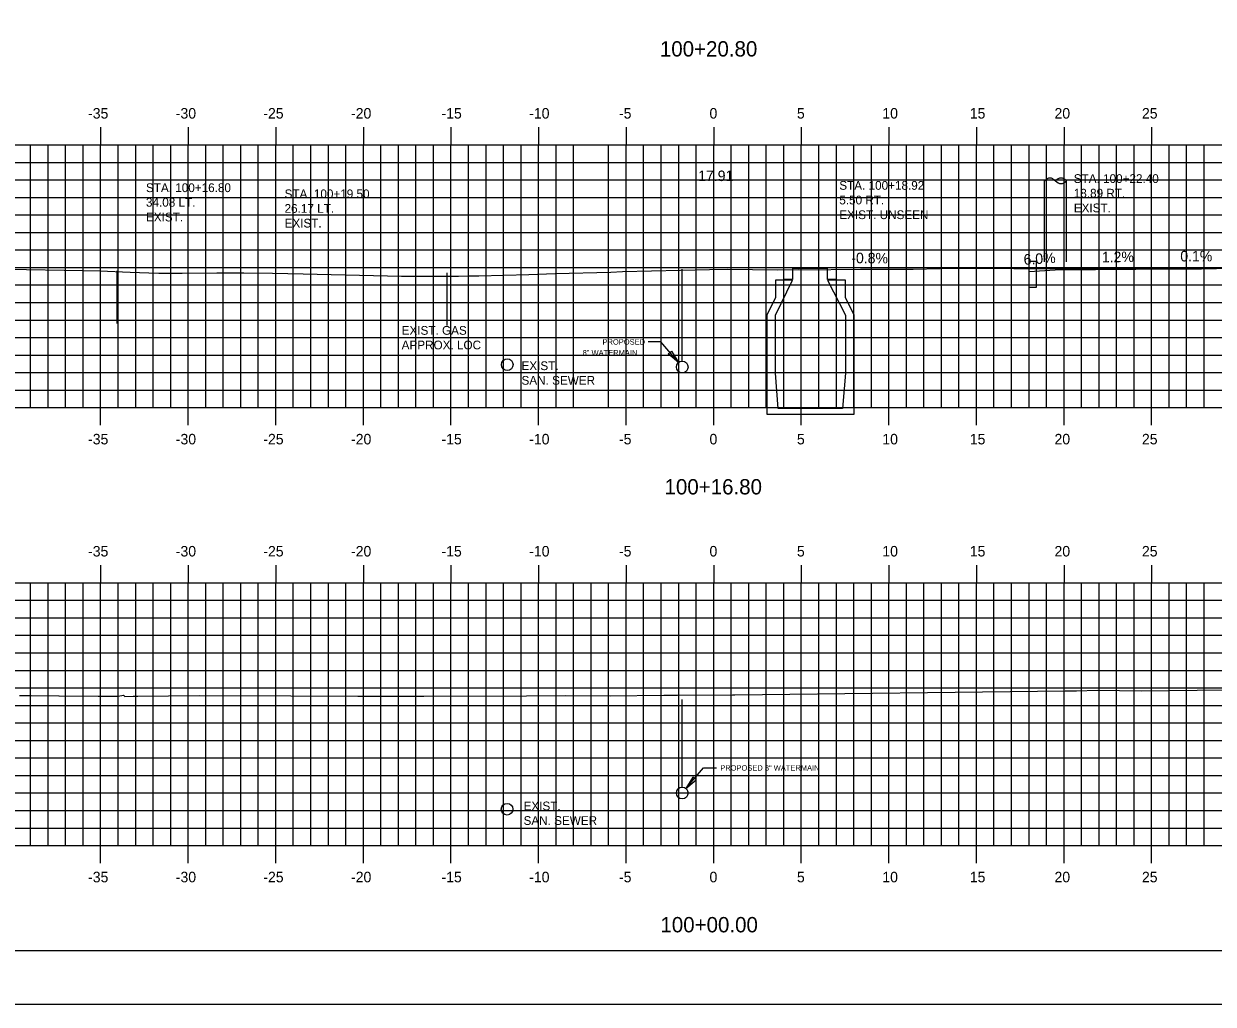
# Model space of a CAD drawing. Extents: x 1023237 to 1023407, y 394697 to 394807.
# Drawn here: x 1023280.3 to 1023348.2, y 394696.5 to 394752.5 of the extents above; entities that cross this region are included whole.
import ezdxf

# ---------------------------------------------------------------- set-up
doc = ezdxf.new("R2010")
doc.units = 0
for name, color, linetype in [('ANNOTATION', 7, 'Continuous'), ('BORDER', 7, 'Continuous'), ('D_Curb_Type_1_Rt', 7, 'Continuous'), ('D_Roadway_Berm', 7, 'Continuous'), ('D_Roadway_Centerline', 7, 'Continuous'), ('D_Roadway_Centerline_Text', 7, 'Continuous'), ('D_Roadway_SlopeLines', 7, 'Continuous'), ('D_Text_Monospaced', 7, 'Continuous'), ('H_V ANNOTATION', 7, 'Continuous'), ('MAJOR', 7, 'Continuous'), ('MINOR', 7, 'Continuous'), ('p-water', 7, 'Continuous'), ('p-water-text', 7, 'Continuous'), ('PLOT BOUNDARY', 7, 'Continuous'), ('S_Drainage_MH', 7, 'Continuous'), ('S_Roadway_Centerline', 7, 'Continuous'), ('S_Utilities_Pole_Power', 7, 'Continuous'), ('S_Utilities_UG_Gas_Line', 7, 'Continuous'), ('S_Utilities_UG_Sanitary_Sewer', 7, 'Continuous')]:
    doc.layers.add(name, color=color, linetype=linetype)

msp = doc.modelspace()

# ---------------------------------------------------------------- linework, layer by layer
at = {"layer": 'BORDER'}
msp.add_line((1023244.664, 394699.607), (1023404.664, 394699.607), dxfattribs=at)
at = {"layer": 'D_Curb_Type_1_Rt'}
msp.add_lwpolyline([(1023338.08, 394738.957), (1023338.08, 394737.457), (1023337.663, 394737.457), (1023337.663, 394738.957)], close=True, dxfattribs=at)
at = {"layer": 'D_Roadway_Berm'}
msp.add_lwpolyline([(1023337.663, 394738.374), (1023339.163, 394738.464)], dxfattribs=at)
at = {"layer": 'D_Roadway_SlopeLines'}
msp.add_lwpolyline([(1023339.163, 394738.464), (1023362.163, 394738.659)], dxfattribs=at)
at = {"layer": 'MAJOR'}
for p, q in [((1023284.663, 394746.609), (1023284.663, 394745.607)), ((1023289.663, 394746.609), (1023289.663, 394745.607)), ((1023294.663, 394746.609), (1023294.663, 394745.607)), ((1023299.663, 394746.609), (1023299.663, 394745.607)), ((1023304.663, 394746.609), (1023304.663, 394745.607)), ((1023309.663, 394746.609), (1023309.663, 394745.607)), ((1023314.663, 394746.609), (1023314.663, 394745.607)), ((1023319.663, 394746.609), (1023319.663, 394745.607)), ((1023324.663, 394746.609), (1023324.663, 394745.607)), ((1023329.663, 394746.609), (1023329.663, 394745.607)), ((1023334.663, 394746.609), (1023334.663, 394745.607)), ((1023339.663, 394746.609), (1023339.663, 394745.607)), ((1023344.663, 394746.609), (1023344.663, 394745.607)), ((1023249.663, 394745.607), (1023389.663, 394745.607)), ((1023284.663, 394730.607), (1023284.663, 394745.607)), ((1023289.663, 394730.607), (1023289.663, 394745.607)), ((1023294.663, 394730.607), (1023294.663, 394745.607)), ((1023299.663, 394730.607), (1023299.663, 394745.607)), ((1023304.663, 394730.607), (1023304.663, 394745.607)), ((1023309.663, 394730.607), (1023309.663, 394745.607)), ((1023314.663, 394730.607), (1023314.663, 394745.607)), ((1023319.663, 394730.607), (1023319.663, 394745.607)), ((1023324.663, 394730.607), (1023324.663, 394745.607)), ((1023329.663, 394730.607), (1023329.663, 394745.607)), ((1023334.663, 394730.607), (1023334.663, 394745.607)), ((1023339.663, 394730.607), (1023339.663, 394745.607)), ((1023344.663, 394730.607), (1023344.663, 394745.607)), ((1023249.663, 394740.607), (1023389.663, 394740.607)), ((1023249.663, 394735.607), (1023389.663, 394735.607)), ((1023249.663, 394730.607), (1023389.663, 394730.607)), ((1023284.663, 394729.605), (1023284.663, 394730.607)), ((1023289.663, 394729.605), (1023289.663, 394730.607)), ((1023294.663, 394729.605), (1023294.663, 394730.607)), ((1023299.663, 394729.605), (1023299.663, 394730.607)), ((1023304.663, 394729.605), (1023304.663, 394730.607)), ((1023309.663, 394729.605), (1023309.663, 394730.607)), ((1023314.663, 394729.605), (1023314.663, 394730.607)), ((1023319.663, 394729.605), (1023319.663, 394730.607)), ((1023324.663, 394729.605), (1023324.663, 394730.607)), ((1023329.663, 394729.605), (1023329.663, 394730.607)), ((1023334.663, 394729.605), (1023334.663, 394730.607)), ((1023339.663, 394729.605), (1023339.663, 394730.607)), ((1023344.663, 394729.605), (1023344.663, 394730.607)), ((1023284.663, 394721.609), (1023284.663, 394720.607)), ((1023289.663, 394721.609), (1023289.663, 394720.607)), ((1023294.663, 394721.609), (1023294.663, 394720.607)), ((1023299.663, 394721.609), (1023299.663, 394720.607)), ((1023304.663, 394721.609), (1023304.663, 394720.607)), ((1023309.663, 394721.609), (1023309.663, 394720.607)), ((1023314.663, 394721.609), (1023314.663, 394720.607)), ((1023319.663, 394721.609), (1023319.663, 394720.607)), ((1023324.663, 394721.609), (1023324.663, 394720.607)), ((1023329.663, 394721.609), (1023329.663, 394720.607)), ((1023334.663, 394721.609), (1023334.663, 394720.607)), ((1023339.663, 394721.609), (1023339.663, 394720.607)), ((1023344.663, 394721.609), (1023344.663, 394720.607)), ((1023249.663, 394720.607), (1023389.663, 394720.607)), ((1023284.663, 394705.607), (1023284.663, 394720.607)), ((1023289.663, 394705.607), (1023289.663, 394720.607)), ((1023294.663, 394705.607), (1023294.663, 394720.607)), ((1023299.663, 394705.607), (1023299.663, 394720.607)), ((1023304.663, 394705.607), (1023304.663, 394720.607)), ((1023309.663, 394705.607), (1023309.663, 394720.607)), ((1023314.663, 394705.607), (1023314.663, 394720.607)), ((1023319.663, 394705.607), (1023319.663, 394720.607)), ((1023324.663, 394705.607), (1023324.663, 394720.607)), ((1023329.663, 394705.607), (1023329.663, 394720.607)), ((1023334.663, 394705.607), (1023334.663, 394720.607)), ((1023339.663, 394705.607), (1023339.663, 394720.607)), ((1023344.663, 394705.607), (1023344.663, 394720.607)), ((1023249.663, 394715.607), (1023389.663, 394715.607)), ((1023249.663, 394710.607), (1023389.663, 394710.607)), ((1023249.663, 394705.607), (1023389.663, 394705.607)), ((1023284.663, 394704.605), (1023284.663, 394705.607)), ((1023289.663, 394704.605), (1023289.663, 394705.607)), ((1023294.663, 394704.605), (1023294.663, 394705.607)), ((1023299.663, 394704.605), (1023299.663, 394705.607)), ((1023304.663, 394704.605), (1023304.663, 394705.607)), ((1023309.663, 394704.605), (1023309.663, 394705.607)), ((1023314.663, 394704.605), (1023314.663, 394705.607)), ((1023319.663, 394704.605), (1023319.663, 394705.607)), ((1023324.663, 394704.605), (1023324.663, 394705.607)), ((1023329.663, 394704.605), (1023329.663, 394705.607)), ((1023334.663, 394704.605), (1023334.663, 394705.607)), ((1023339.663, 394704.605), (1023339.663, 394705.607)), ((1023344.663, 394704.605), (1023344.663, 394705.607))]:
    msp.add_line(p, q, dxfattribs=at)
at = {"layer": 'MINOR'}
for p, q in [((1023280.663, 394730.607), (1023280.663, 394745.607)), ((1023281.663, 394730.607), (1023281.663, 394745.607)), ((1023282.663, 394730.607), (1023282.663, 394745.607)), ((1023283.663, 394730.607), (1023283.663, 394745.607)), ((1023285.663, 394730.607), (1023285.663, 394745.607)), ((1023286.663, 394730.607), (1023286.663, 394745.607)), ((1023287.663, 394730.607), (1023287.663, 394745.607)), ((1023288.663, 394730.607), (1023288.663, 394745.607)), ((1023290.663, 394730.607), (1023290.663, 394745.607)), ((1023291.663, 394730.607), (1023291.663, 394745.607)), ((1023292.663, 394730.607), (1023292.663, 394745.607)), ((1023293.663, 394730.607), (1023293.663, 394745.607)), ((1023295.663, 394730.607), (1023295.663, 394745.607)), ((1023296.663, 394730.607), (1023296.663, 394745.607)), ((1023297.663, 394730.607), (1023297.663, 394745.607)), ((1023298.663, 394730.607), (1023298.663, 394745.607)), ((1023300.663, 394730.607), (1023300.663, 394745.607)), ((1023301.663, 394730.607), (1023301.663, 394745.607)), ((1023302.663, 394730.607), (1023302.663, 394745.607)), ((1023303.663, 394730.607), (1023303.663, 394745.607)), ((1023305.663, 394730.607), (1023305.663, 394745.607)), ((1023306.663, 394730.607), (1023306.663, 394745.607)), ((1023307.663, 394730.607), (1023307.663, 394745.607)), ((1023308.663, 394730.607), (1023308.663, 394745.607)), ((1023310.663, 394730.607), (1023310.663, 394745.607)), ((1023311.663, 394730.607), (1023311.663, 394745.607)), ((1023313.663, 394730.607), (1023313.663, 394745.607)), ((1023315.663, 394730.607), (1023315.663, 394745.607)), ((1023316.663, 394730.607), (1023316.663, 394745.607)), ((1023317.663, 394730.607), (1023317.663, 394745.607)), ((1023318.663, 394730.607), (1023318.663, 394745.607)), ((1023320.663, 394730.607), (1023320.663, 394745.607)), ((1023321.663, 394730.607), (1023321.663, 394745.607)), ((1023322.663, 394730.607), (1023322.663, 394745.607)), ((1023323.663, 394730.607), (1023323.663, 394745.607)), ((1023325.663, 394730.607), (1023325.663, 394745.607)), ((1023326.663, 394730.607), (1023326.663, 394745.607)), ((1023327.663, 394730.607), (1023327.663, 394745.607)), ((1023328.663, 394730.607), (1023328.663, 394745.607)), ((1023330.663, 394730.607), (1023330.663, 394745.607)), ((1023331.663, 394730.607), (1023331.663, 394745.607)), ((1023332.663, 394730.607), (1023332.663, 394745.607)), ((1023333.663, 394730.607), (1023333.663, 394745.607)), ((1023335.663, 394730.607), (1023335.663, 394745.607)), ((1023336.663, 394730.607), (1023336.663, 394745.607)), ((1023337.663, 394730.607), (1023337.663, 394745.607)), ((1023338.663, 394730.607), (1023338.663, 394745.607)), ((1023340.663, 394730.607), (1023340.663, 394745.607)), ((1023341.663, 394730.607), (1023341.663, 394745.607)), ((1023342.663, 394730.607), (1023342.663, 394745.607)), ((1023343.663, 394730.607), (1023343.663, 394745.607)), ((1023345.663, 394730.607), (1023345.663, 394745.607)), ((1023346.663, 394730.607), (1023346.663, 394745.607)), ((1023347.663, 394730.607), (1023347.663, 394745.607)), ((1023249.663, 394744.607), (1023389.663, 394744.607)), ((1023249.663, 394743.607), (1023389.663, 394743.607)), ((1023249.663, 394742.607), (1023389.663, 394742.607)), ((1023249.663, 394741.607), (1023389.663, 394741.607)), ((1023249.663, 394739.607), (1023389.663, 394739.607)), ((1023249.663, 394738.607), (1023389.663, 394738.607)), ((1023249.663, 394737.607), (1023389.663, 394737.607)), ((1023249.663, 394736.607), (1023389.663, 394736.607)), ((1023249.663, 394734.607), (1023389.663, 394734.607)), ((1023249.663, 394733.607), (1023389.663, 394733.607)), ((1023249.663, 394732.607), (1023389.663, 394732.607)), ((1023249.663, 394731.607), (1023389.663, 394731.607)), ((1023280.663, 394705.607), (1023280.663, 394720.607)), ((1023281.663, 394705.607), (1023281.663, 394720.607)), ((1023282.663, 394705.607), (1023282.663, 394720.607)), ((1023283.663, 394705.607), (1023283.663, 394720.607)), ((1023285.663, 394705.607), (1023285.663, 394720.607)), ((1023286.663, 394705.607), (1023286.663, 394720.607)), ((1023287.663, 394705.607), (1023287.663, 394720.607)), ((1023288.663, 394705.607), (1023288.663, 394720.607)), ((1023290.663, 394705.607), (1023290.663, 394720.607)), ((1023291.663, 394705.607), (1023291.663, 394720.607)), ((1023292.663, 394705.607), (1023292.663, 394720.607)), ((1023293.663, 394705.607), (1023293.663, 394720.607)), ((1023295.663, 394705.607), (1023295.663, 394720.607)), ((1023296.663, 394705.607), (1023296.663, 394720.607)), ((1023297.663, 394705.607), (1023297.663, 394720.607)), ((1023298.663, 394705.607), (1023298.663, 394720.607)), ((1023300.663, 394705.607), (1023300.663, 394720.607)), ((1023301.663, 394705.607), (1023301.663, 394720.607)), ((1023302.663, 394705.607), (1023302.663, 394720.607)), ((1023303.663, 394705.607), (1023303.663, 394720.607)), ((1023305.663, 394705.607), (1023305.663, 394720.607)), ((1023306.663, 394705.607), (1023306.663, 394720.607)), ((1023307.663, 394705.607), (1023307.663, 394720.607)), ((1023308.663, 394705.607), (1023308.663, 394720.607)), ((1023310.663, 394705.607), (1023310.663, 394720.607)), ((1023311.663, 394705.607), (1023311.663, 394720.607)), ((1023312.663, 394705.607), (1023312.663, 394720.607)), ((1023313.663, 394705.607), (1023313.663, 394720.607)), ((1023315.663, 394705.607), (1023315.663, 394720.607)), ((1023316.663, 394705.607), (1023316.663, 394720.607)), ((1023317.663, 394705.607), (1023317.663, 394720.607)), ((1023318.663, 394705.607), (1023318.663, 394720.607)), ((1023320.663, 394705.607), (1023320.663, 394720.607)), ((1023321.663, 394705.607), (1023321.663, 394720.607)), ((1023322.663, 394705.607), (1023322.663, 394720.607)), ((1023323.663, 394705.607), (1023323.663, 394720.607)), ((1023325.663, 394705.607), (1023325.663, 394720.607)), ((1023326.663, 394705.607), (1023326.663, 394720.607)), ((1023327.663, 394705.607), (1023327.663, 394720.607)), ((1023328.663, 394705.607), (1023328.663, 394720.607)), ((1023330.663, 394705.607), (1023330.663, 394720.607)), ((1023331.663, 394705.607), (1023331.663, 394720.607)), ((1023332.663, 394705.607), (1023332.663, 394720.607)), ((1023333.663, 394705.607), (1023333.663, 394720.607)), ((1023335.663, 394705.607), (1023335.663, 394720.607)), ((1023336.663, 394705.607), (1023336.663, 394720.607)), ((1023337.663, 394705.607), (1023337.663, 394720.607)), ((1023338.663, 394705.607), (1023338.663, 394720.607)), ((1023340.663, 394705.607), (1023340.663, 394720.607)), ((1023341.663, 394705.607), (1023341.663, 394720.607)), ((1023342.663, 394705.607), (1023342.663, 394720.607)), ((1023343.663, 394705.607), (1023343.663, 394720.607)), ((1023345.663, 394705.607), (1023345.663, 394720.607)), ((1023346.663, 394705.607), (1023346.663, 394720.607)), ((1023347.663, 394705.607), (1023347.663, 394720.607)), ((1023249.663, 394719.607), (1023389.663, 394719.607)), ((1023249.663, 394718.607), (1023389.663, 394718.607)), ((1023249.663, 394717.607), (1023389.663, 394717.607)), ((1023249.663, 394716.607), (1023389.663, 394716.607)), ((1023249.663, 394714.607), (1023389.663, 394714.607)), ((1023249.663, 394713.607), (1023389.663, 394713.607)), ((1023249.663, 394712.607), (1023389.663, 394712.607)), ((1023249.663, 394711.607), (1023389.663, 394711.607)), ((1023249.663, 394709.607), (1023389.663, 394709.607)), ((1023249.663, 394708.607), (1023389.663, 394708.607)), ((1023249.663, 394707.607), (1023389.663, 394707.607)), ((1023249.663, 394706.607), (1023389.663, 394706.607))]:
    msp.add_line(p, q, dxfattribs=at)
at = {"layer": 'p-water'}
msp.add_line((1023317.865, 394733.257), (1023317.865, 394738.507), dxfattribs=at)
msp.add_lwpolyline([(1023317.865, 394708.936), (1023317.865, 394713.936)], dxfattribs=at)
for centre in [(1023317.865, 394732.924), (1023317.865, 394708.603)]:
    msp.add_circle(centre, 0.333, dxfattribs=at)
at = {"layer": 'p-water-text'}
for points in [[(1023317.649, 394733.178), (1023316.646, 394734.355), (1023315.913, 394734.355)], [(1023318.079, 394708.859), (1023319.082, 394710.036), (1023319.815, 394710.036)]]:
    msp.add_lwpolyline(points, dxfattribs=at)
for points in [[(1023317.068, 394733.668), (1023317.258, 394733.83), (1023317.649, 394733.178)], [(1023318.66, 394709.349), (1023318.47, 394709.511), (1023318.079, 394708.859)]]:
    msp.add_lwpolyline(points, close=True, dxfattribs=at)
at = {"layer": 'PLOT BOUNDARY'}
msp.add_lwpolyline([(1023236.57, 394696.548), (1023406.57, 394696.548), (1023406.57, 394806.548), (1023236.57, 394806.548)], close=True, dxfattribs=at)
at = {"layer": 'S_Drainage_MH'}
for p, q in [((1023324.165, 394737.879), (1023323.181, 394737.879)), ((1023323.181, 394737.879), (1023323.181, 394736.895)), ((1023323.181, 394735.878), (1023324.165, 394737.879)), ((1023327.183, 394737.879), (1023326.166, 394737.879)), ((1023326.166, 394737.879), (1023327.183, 394735.878)), ((1023327.183, 394736.895), (1023327.183, 394737.879)), ((1023323.181, 394736.895), (1023322.688, 394735.878)), ((1023327.675, 394735.878), (1023327.183, 394736.895)), ((1023322.688, 394735.878), (1023322.688, 394730.235)), ((1023323.181, 394732.564), (1023323.181, 394735.878)), ((1023327.183, 394735.878), (1023327.183, 394732.564)), ((1023327.675, 394730.235), (1023327.675, 394735.878)), ((1023323.345, 394730.563), (1023323.181, 394732.564)), ((1023327.183, 394732.564), (1023327.019, 394730.563)), ((1023322.688, 394730.235), (1023327.675, 394730.235)), ((1023327.019, 394730.563), (1023323.345, 394730.563))]:
    msp.add_line(p, q, dxfattribs=at)
msp.add_lwpolyline([(1023326.658, 394737.921), (1023326.166, 394737.921), (1023326.166, 394738.544), (1023324.165, 394738.544), (1023324.165, 394737.921), (1023323.673, 394737.921)], dxfattribs=at)
at = {"layer": 'S_Roadway_Centerline'}
for points in [[(1023279.356, 394738.503), (1023283.639, 394738.442), (1023284.613, 394738.41), (1023286.353, 394738.34), (1023287.409, 394738.298), (1023287.978, 394738.275), (1023289.319, 394738.283), (1023291.289, 394738.299), (1023292.834, 394738.302), (1023294.482, 394738.289), (1023296.226, 394738.238), (1023301.837, 394738.105), (1023302.283, 394738.114), (1023303.112, 394738.115), (1023305.088, 394738.108), (1023305.641, 394738.124), (1023306.25, 394738.132), (1023309.111, 394738.214), (1023310.616, 394738.254), (1023313.789, 394738.348), (1023314.452, 394738.382), (1023319.414, 394738.497), (1023320.465, 394738.51), (1023323.281, 394738.475), (1023324.509, 394738.493), (1023324.674, 394738.476), (1023328.034, 394738.512), (1023331.043, 394738.506), (1023332.593, 394738.551), (1023335.834, 394738.561), (1023336.595, 394738.56), (1023336.793, 394738.545), (1023337.2, 394738.549), (1023337.268, 394738.548), (1023341.123, 394738.542), (1023343.602, 394738.533), (1023345.21, 394738.526), (1023347.511, 394738.538), (1023349.628, 394738.643)], [(1023280.039, 394714.166), (1023280.7, 394714.164), (1023282.28, 394714.155), (1023282.295, 394714.156), (1023284.525, 394714.138), (1023284.92, 394714.138), (1023285.666, 394714.125), (1023285.96, 394714.182), (1023286.037, 394714.123), (1023286.522, 394714.125), (1023286.746, 394714.125), (1023286.781, 394714.125), (1023290.283, 394714.168), (1023295.53, 394714.143), (1023299.347, 394714.131), (1023300.757, 394714.128), (1023301.054, 394714.139), (1023301.132, 394714.128), (1023301.816, 394714.125), (1023302.56, 394714.13), (1023303.117, 394714.136), (1023308.973, 394714.16), (1023311.214, 394714.164), (1023313.757, 394714.161), (1023316.809, 394714.184), (1023317.308, 394714.186), (1023317.591, 394714.19), (1023320.732, 394714.2), (1023320.758, 394714.2), (1023320.876, 394714.202), (1023339.734, 394714.446), (1023340.381, 394714.433), (1023341.573, 394714.469), (1023344.084, 394714.436), (1023347.262, 394714.469), (1023348.934, 394714.493)]]:
    msp.add_lwpolyline(points, dxfattribs=at)
at = {"layer": 'S_Utilities_Pole_Power'}
for p, q in [((1023338.553, 394743.551), (1023338.709, 394743.661)), ((1023339.021, 394743.661), (1023339.177, 394743.551)), ((1023339.334, 394743.661), (1023339.177, 394743.551)), ((1023339.803, 394743.551), (1023339.647, 394743.661)), ((1023338.553, 394738.932), (1023338.549, 394743.551)), ((1023339.177, 394743.551), (1023339.334, 394743.44)), ((1023339.647, 394743.44), (1023339.803, 394743.551)), ((1023339.803, 394738.932), (1023339.799, 394743.551))]:
    msp.add_line(p, q, dxfattribs=at)
for centre, start, end in [((1023338.865, 394743.441), 90, 125.26439), ((1023338.865, 394743.441), 54.73561, 90), ((1023339.49, 394743.441), 90, 125.26439), ((1023339.49, 394743.441), 54.73561, 90), ((1023339.49, 394743.662), 234.73561, 270), ((1023339.49, 394743.662), 270, 305.26439)]:
    msp.add_arc(centre, 0.271, start, end, dxfattribs=at)
at = {"layer": 'S_Utilities_UG_Gas_Line'}
for p, q in [((1023285.585, 394738.412), (1023285.585, 394735.412)), ((1023304.423, 394738.296), (1023304.423, 394735.296))]:
    msp.add_line(p, q, dxfattribs=at)
at = {"layer": 'S_Utilities_UG_Sanitary_Sewer'}
for centre in [(1023307.878, 394733.06), (1023307.867, 394707.68)]:
    msp.add_circle(centre, 0.333, dxfattribs=at)

# ---------------------------------------------------------------- texts
at = {"layer": 'ANNOTATION'}
for s, rotation, p in [('0.1%', 0.06224, (1023346.299, 394738.952)), ('-0.8%', 359.55769, (1023327.515, 394738.852)), ('6.0%', 3.43363, (1023337.371, 394738.758)), ('1.2%', 0.71562, (1023341.826, 394738.897))]:
    msp.add_text(s, height=0.6, rotation=rotation, dxfattribs=at).set_placement(p)
at = {"layer": 'D_Roadway_Centerline'}
for s, p in [('C', (1023319.658, 394738.513)), ('L', (1023319.663, 394738.506)), ('C', (1023319.643, 394713.927)), ('L', (1023319.648, 394713.92)), ('C', (1023319.658, 394713.927)), ('L', (1023319.663, 394713.92))]:
    msp.add_text(s, height=0.0146, dxfattribs=at).set_placement(p)
at = {"layer": 'D_Roadway_Centerline_Text'}
msp.add_text('17.91', height=0.6, dxfattribs=at).set_placement((1023318.775, 394743.539))
at = {"layer": 'D_Text_Monospaced'}
for s, height, p in [('STA. 100+22.40', 0.49998, (1023340.219, 394743.43)), ('STA. 100+16.80', 0.49998, (1023287.251, 394742.91)), ('STA. 100+19.50', 0.49998, (1023295.164, 394742.561)), ('STA. 100+18.92', 0.49998, (1023326.832, 394743.042)), ('18.89 RT.', 0.5, (1023340.219, 394742.596)), ('34.08 LT.', 0.5, (1023287.251, 394742.076)), ('5.50 RT.', 0.5, (1023326.832, 394742.208)), ('EXIST. ', 0.5, (1023340.219, 394741.756)), ('EXIST. ', 0.5, (1023287.251, 394741.236)), ('26.17 LT.', 0.5, (1023295.164, 394741.727)), ('EXIST. UNSEEN', 0.49998, (1023326.832, 394741.368)), ('EXIST. ', 0.5, (1023295.164, 394740.887)), ('EXIST. GAS', 0.5, (1023301.847, 394734.765)), ('APPROX. LOC', 0.49998, (1023301.847, 394733.931)), ('EXIST. ', 0.5, (1023308.69, 394732.746)), ('SAN. SEWER', 0.5, (1023308.69, 394731.913)), ('EXIST. ', 0.5, (1023308.807, 394707.615)), ('SAN. SEWER', 0.5, (1023308.807, 394706.782))]:
    msp.add_text(s, height=height, dxfattribs=at).set_placement(p)
at = {"layer": 'H_V ANNOTATION'}
for s, height, p in [('100+20.80', 0.875, (1023316.589, 394750.65)), ('-35', 0.6, (1023283.944, 394747.107)), ('-30', 0.6, (1023288.952, 394747.107)), ('-25', 0.6, (1023293.949, 394747.107)), ('-20', 0.6, (1023298.957, 394747.107)), ('-15', 0.6, (1023304.12, 394747.107)), ('-10', 0.6, (1023309.128, 394747.107)), ('-5', 0.6, (1023314.254, 394747.107)), ('0', 0.6, (1023319.422, 394747.107)), ('5', 0.6, (1023324.414, 394747.107)), ('10', 0.6, (1023329.289, 394747.107)), ('15', 0.6, (1023334.281, 394747.107)), ('20', 0.6, (1023339.117, 394747.107)), ('25', 0.6, (1023344.109, 394747.107)), ('-35', 0.6, (1023283.944, 394728.507)), ('-30', 0.6, (1023288.952, 394728.507)), ('-25', 0.6, (1023293.949, 394728.507)), ('-20', 0.6, (1023298.957, 394728.507)), ('-15', 0.6, (1023304.12, 394728.507)), ('-10', 0.6, (1023309.128, 394728.507)), ('-5', 0.6, (1023314.254, 394728.507)), ('0', 0.6, (1023319.422, 394728.507)), ('5', 0.6, (1023324.414, 394728.507)), ('10', 0.6, (1023329.289, 394728.507)), ('15', 0.6, (1023334.281, 394728.507)), ('20', 0.6, (1023339.117, 394728.507)), ('25', 0.6, (1023344.109, 394728.507)), ('100+16.80', 0.875, (1023316.855, 394725.65)), ('-35', 0.6, (1023283.944, 394722.107)), ('-30', 0.6, (1023288.952, 394722.107)), ('-25', 0.6, (1023293.949, 394722.107)), ('-20', 0.6, (1023298.957, 394722.107)), ('-15', 0.6, (1023304.12, 394722.107)), ('-10', 0.6, (1023309.128, 394722.107)), ('-5', 0.6, (1023314.254, 394722.107)), ('0', 0.6, (1023319.422, 394722.107)), ('5', 0.6, (1023324.414, 394722.107)), ('10', 0.6, (1023329.289, 394722.107)), ('15', 0.6, (1023334.281, 394722.107)), ('20', 0.6, (1023339.117, 394722.107)), ('25', 0.6, (1023344.109, 394722.107)), ('-35', 0.6, (1023283.944, 394703.507)), ('-30', 0.6, (1023288.952, 394703.507)), ('-25', 0.6, (1023293.949, 394703.507)), ('-20', 0.6, (1023298.957, 394703.507)), ('-15', 0.6, (1023304.12, 394703.507)), ('-10', 0.6, (1023309.128, 394703.507)), ('-5', 0.6, (1023314.254, 394703.507)), ('0', 0.6, (1023319.422, 394703.507)), ('5', 0.6, (1023324.414, 394703.507)), ('10', 0.6, (1023329.289, 394703.507)), ('15', 0.6, (1023334.281, 394703.507)), ('20', 0.6, (1023339.117, 394703.507)), ('25', 0.6, (1023344.109, 394703.507)), ('100+00.00', 0.875, (1023316.62, 394700.65))]:
    msp.add_text(s, height=height, dxfattribs=at).set_placement(p)
at = {"layer": 'p-water-text'}
for s, p in [('PROPOSED ', (1023313.316, 394734.201)), ('8" WATERMAIN', (1023312.179, 394733.581)), ('PROPOSED 8" WATERMAIN', (1023320.035, 394709.883))]:
    msp.add_text(s, height=0.31, dxfattribs=at).set_placement(p)

doc.saveas('drawing.dxf')
